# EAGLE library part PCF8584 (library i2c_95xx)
I²C Bus Controller
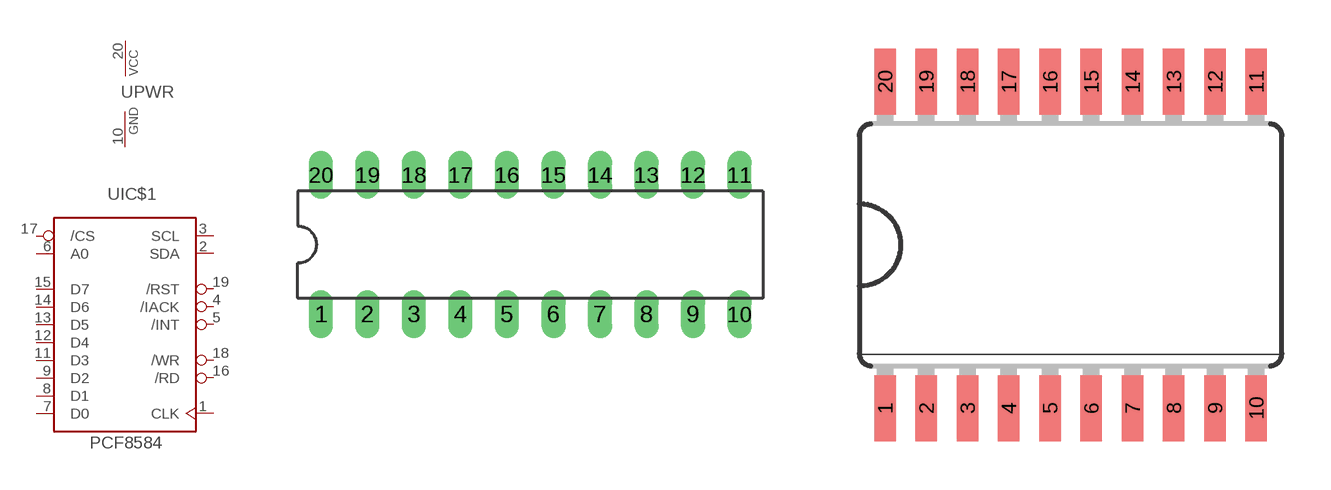
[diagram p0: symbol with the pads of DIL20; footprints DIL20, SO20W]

Designator prefix -; gates IC$1=PCF8584 PWR=PWRN

## PCF8584P  [DIL20]
1  IC$1:CLK  in
2  IC$1:SDA
3  IC$1:SCL
4  IC$1:/IACK  in
5  IC$1:/INT  out
6  IC$1:A0  in
7  IC$1:D0
8  IC$1:D1
9  IC$1:D2
10  PWR:GND  pwr
11  IC$1:D3
12  IC$1:D4
13  IC$1:D5
14  IC$1:D6
15  IC$1:D7
16  IC$1:/RD
17  IC$1:/CS  in
18  IC$1:/WR  in
19  IC$1:/RST
20  PWR:VCC  pwr

## PCF8584T  [SO20W]
Pads as for DIL20

## Footprint DIL20 (pad centres in mm)
drill 0.813 long: 1 -11.43,-3.81; 2 -8.89,-3.81; 3 -6.35,-3.81; 4 -3.81,-3.81; 5 -1.27,-3.81; 6 1.27,-3.81; 7 3.81,-3.81; 8 6.35,-3.81; 9 8.89,-3.81; 10 11.43,-3.81; 11 11.43,3.81; 12 8.89,3.81; 13 6.35,3.81; 14 3.81,3.81; 15 1.27,3.81; 16 -1.27,3.81; 17 -3.81,3.81; 18 -6.35,3.81; 19 -8.89,3.81; 20 -11.43,3.81

## Footprint SO20W (pad centres in mm)
smd 0.66 x 2.032: 1 -5.715,-5.029; 2 -4.445,-5.029; 3 -3.175,-5.029; 4 -1.905,-5.029; 5 -0.635,-5.029; 6 0.635,-5.029; 7 1.905,-5.029; 8 3.175,-5.029; 9 4.445,-5.029; 10 5.715,-5.029; 11 5.715,5.029; 12 4.445,5.029; 13 3.175,5.029; 14 1.905,5.029; 15 0.635,5.029; 16 -0.635,5.029; 17 -1.905,5.029; 18 -3.175,5.029; 19 -4.445,5.029; 20 -5.715,5.029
